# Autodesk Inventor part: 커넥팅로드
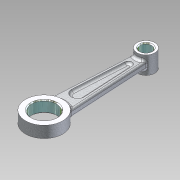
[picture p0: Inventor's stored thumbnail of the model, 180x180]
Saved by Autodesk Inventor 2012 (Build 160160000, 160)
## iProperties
Manager: KYOUNG IL JANG
Company: 한국ATC센터
Created: 2012-10
Part Number: 커넥팅로드
Document SubType Name: Modeling
Density: 1 g/cm^3
Checked By: KYOUNG IL JANG
Vendor: CBT Solutions
Designer: KYOUNG IL JANG
Material: 기본값
Author: KYOUNG IL JANG
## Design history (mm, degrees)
sketch "스케치1"
  geometry: L1 (-19.879, 82.758)-(-19.879, 197.758); L2 (-27.379, 191.144)-(-32.379, 99.633); L3 (-12.379, 191.144)-(-7.379, 99.633); C1 r 14 at (-19.879, 82.758); C2 r 6.5 at (-19.879, 197.758); A1 r 19 centre (-19.879, 82.758) between (-20.11, 101.757) and (-19.649, 63.76) reference; A2 r 21 centre (-19.879, 82.758) between (-32.379, 99.633) and (-7.379, 99.633); A3 r 10 centre (-19.879, 197.758) between (-27.379, 191.144) and (-12.379, 191.144); 1 further point
  constraints: 6 end point, 4 centre point, 4 coincident, 4 point on circle, 2 horizontal alignment, 1 equal length, 1 vertical
  dimensions: "d0" = 28 diameter of C1; "d1" = 42 diameter of A2; "d4" = 115 distance of L1.end C1.centre; "d5" = 20 diameter of A3; "d6" = 13 diameter of C2; "d7" = 25 distance of L3.end L2.end; "d8" = 15 distance of L3.start L2.start
  node "참조1"
extrude "돌출1" new body sketch "스케치1" stored distance "d2" = 13; taper "d3" = 0 deg
extrude "돌출2" join sketch "스케치1" stored distance "d9" = 20; taper "d10" = 0 deg
extrude "돌출3" join sketch "스케치1" stored distance "d11" = 8; taper "d12" = 0 deg
sketch "스케치2"
  geometry: L1 (7.379, 99.633)-(12.379, 191.144) reference; L2 (27.379, 191.144)-(32.379, 99.633) reference; L3 (27.197, 121.158)-(24.092, 177.989); L4 (15.667, 177.989)-(12.561, 121.158); A1 r 21 centre (19.879, 82.758) between (7.379, 99.633) and (32.379, 99.633) reference; A2 r 7.329 centre (19.879, 120.758) between (12.561, 121.158) and (27.197, 121.158); A3 r 4.219 centre (19.879, 177.758) between (24.092, 177.989) and (15.667, 177.989); A4 r 10 centre (19.879, 197.758) between (12.379, 191.144) and (27.379, 191.144) reference; 2 further points
  constraints: 4 end point, 4 point on circle, 4 tangent, 2 centre point, 2 parallel, 1 coincident, 3 other
  dimensions: "d16" = 38 distance of A2.centre A1.centre; "d17" = 4 distance between parallel lines of L2 L3; "d18" = 4 distance between parallel lines of L4 L1; "d25" = 20 distance of A3.centre A4.centre
extrude "돌출4" cut sketch "스케치2" distance "d19" = 5; taper "d20" = 0 deg
fillet "모깎기1" dims "d21" = 2
fillet "모깎기2" dims "d22" = 3
fillet "모깎기3" dims "d23" = 3
chamfer "모따기1" distance "d26" = 1; stored, may be unused: second distance "d27" = 2, angle "d28" = 45 deg
chamfer "모따기2" distance "d29" = 1; stored, may be unused: second distance "d30" = 2, angle "d31" = 45 deg
node "솔리드1"
mirror "대칭1"
other parameters: "d13" = 5, "d14" = 5
